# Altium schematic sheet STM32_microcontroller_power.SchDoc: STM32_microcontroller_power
size A3; DocumentNumber: MB1312; Revision: A-03; SheetNumber: 4; SheetTotal: 9; Project: NUCLEO-L4P5ZG
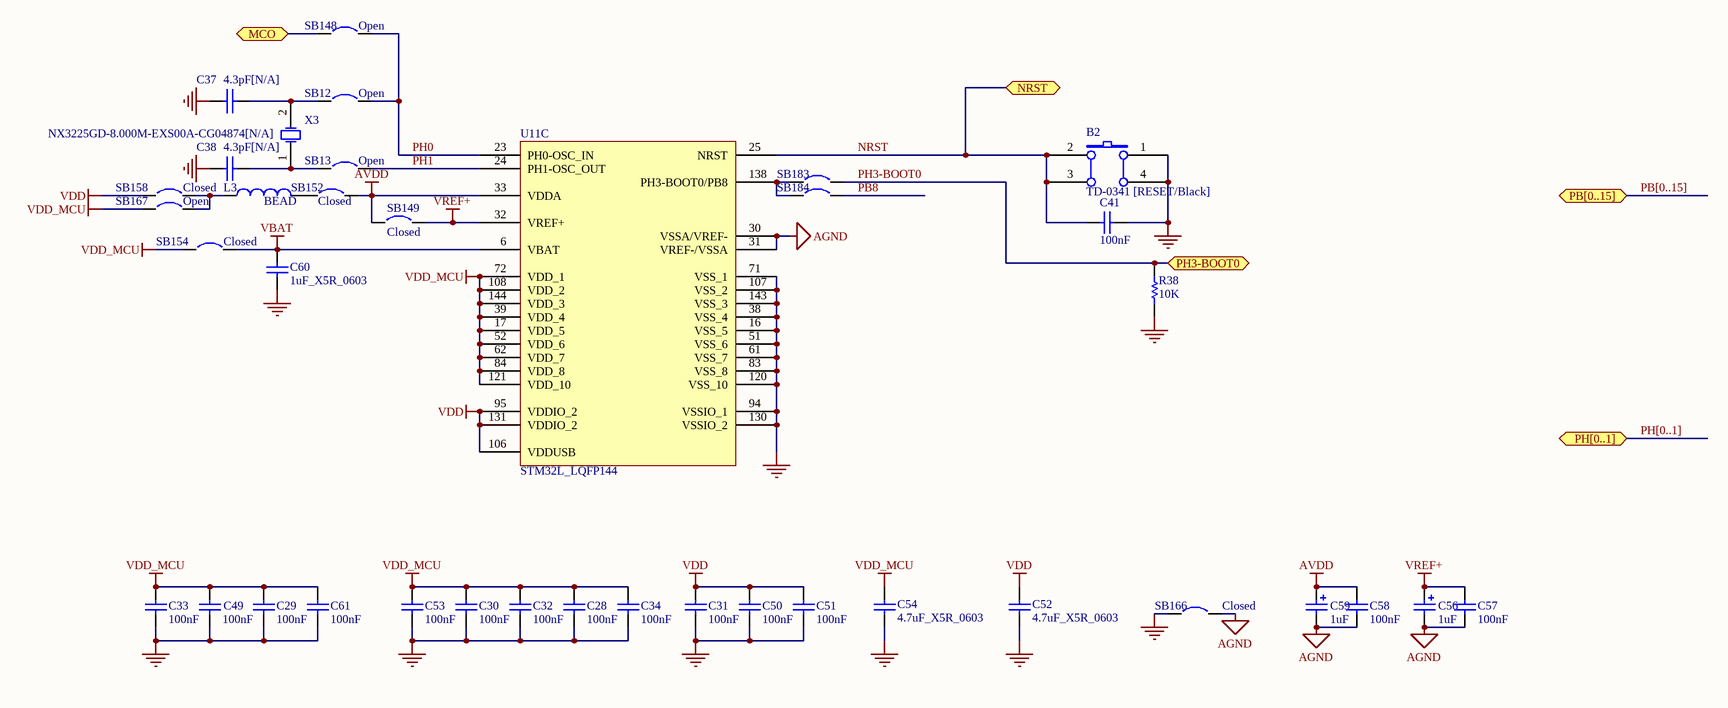
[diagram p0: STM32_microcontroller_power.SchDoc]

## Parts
B2  TD-0341 [RESET/Black]  [PB-6X6mm-Black]
C28  100nF  [0603C]
C29  100nF  [0603C]
C30  100nF  [0603C]
C31  100nF  [0603C]
C32  100nF  [0603C]
C33  100nF  [0603C]
C34  100nF  [0603C]
C37  4.3pF[N/A]  [0603C]
C38  4.3pF[N/A]  [0603C]
C41  100nF  [0603C]
C49  100nF  [0603C]
C50  100nF  [0603C]
C51  100nF  [0603C]
C52  4.7uF_X5R_0603  [0603C]
C53  100nF  [0603C]
C54  4.7uF_X5R_0603  [0603C]
C56  value 1uF  [TAN-A]  (hidden comment: TAJA105K016R)
C57  100nF  [0603C]
C58  100nF  [0603C]
C59  value 1uF  [TAN-A]  (hidden comment: TAJA105K016R)
C60  1uF_X5R_0603  [0603C]
C61  100nF  [0603C]
L3  BEAD  [0603L]
R38  10K  [0603R]
SB12  Open  [SB_0603]
SB13  Open  [SB_0603]
SB148  Open  [SB_0603]
SB149  Closed  [SB_0603]
SB152  Closed  [SB_0603]
SB154  Closed  [SB_0603]
SB158  Closed  [SB_0603]
SB166  Closed  [SB_0603]
SB167  Open  [SB_0603]
SB183  Circuit Breaker  [SB_0603]  (value not drawn)
SB184  Circuit Breaker  [SB_0603]  (value not drawn)
U11  STM32L_LQFP144  [LQFP144_0R5_SKT]  (part C of 3)
X3  NX3225GD-8.000M-EXS00A-CG04874[N/A]  [OSC_2SM_3R2x2R5]

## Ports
MCO, NRST, PB[0..15] (bidir), PH3-BOOT0, PH[0..1] (bidir)

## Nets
AGND: C56.2 C57.2 C58.2 C59.2 SB166.2 U11.30(VSSA/VREF-) U11.31(VREF-/VSSA)
AVDD: C58.1 C59.1 SB149.1 SB152.2 U11.33(VDDA)
GND: B2.1(A0) B2.4(A1) C28.2 C29.2 C30.2 C31.2 C32.2 C33.2 C34.2 C37.2 C38.2 C41.1 C49.2 C50.2 C51.2 C52.2 C53.2 C54.2 C60.2 C61.2 R38.2 SB166.1 U11.16(VSS_5) U11.38(VSS_4) U11.51(VSS_6) U11.61(VSS_7) U11.71(VSS_1) U11.83(VSS_8) U11.94(VSSIO_1) U11.107(VSS_2) U11.120(VSS_10) U11.130(VSSIO_2) U11.143(VSS_3)
VBAT: C60.1 SB154.2 U11.6(VBAT)
VDD: C31.1 C50.1 C51.1 C52.1 SB158.1 U11.95(VDDIO_2) U11.106(VDDUSB) U11.131(VDDIO_2)
VDD_MCU: C28.1 C29.1 C30.1 C32.1 C33.1 C34.1 C49.1 C53.1 C54.1 C61.1 SB154.1 SB167.1 U11.17(VDD_5) U11.39(VDD_4) U11.52(VDD_6) U11.62(VDD_7) U11.72(VDD_1) U11.84(VDD_8) U11.108(VDD_2) U11.121(VDD_10) U11.144(VDD_3)
VREF+: C56.1 C57.1 SB149.2 U11.32(VREF+)
MCO: SB148.2 ; port MCO
NRST: B2.2(B0) B2.3(B1) C41.2 U11.25(NRST) ; port NRST
PB8: SB184.2
PH0: SB12.2 SB148.1 U11.23(PH0-OSC_IN)
PH1: SB13.2 U11.24(PH1-OSC_OUT)
PH3-BOOT0: R38.1 SB183.2 ; port PH3-BOOT0
NetC37_1: C37.1 SB12.1 X3.2(OSC2)
NetC38_1: C38.1 SB13.1 X3.1(OSC1)
NetL3_1: L3.1 SB158.2 SB167.2
NetL3_2: L3.2 SB152.1
NetSB183_1: SB183.1 SB184.1 U11.138(PH3-BOOT0/PB8)

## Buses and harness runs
bus PB[0..15] = port PB[0..15]
bus PH[0..1] = port PH[0..1]

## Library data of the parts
B2 = SW PUSHBUTTON: SE PUSHBUTTON
C28-C34 C49-C51 C53 C57 C58 C61 = Cap: Capacitor; Value: 10nF
C37 C38 = CAP: Capacitor
C41 = CAP: Capacitor; Value: 100pF
C52 C54 = CAP SMD 0603  X5R 1µF 25V 10%: 0603  X5R 4.7uF; Value: 1µF; Rated voltage: 25V; Tolerance: 10%
C56 C59 = Cap Pol1: Tan Capacitor,1uF,10%,16V,Tan-A,TAJA105K016R; Manuf_1: AVX; Ordered by: Subcon; ECCN_US/EU: NA
C60 = CAP SMD 0603  X5R 1µF 25V 10%: 0603  X5R 1µF; Rated voltage: 25V; Tolerance: 10%
L3 = Inductor: Value: 100uH
R38 = res1: Resistor; Value: 1K
SB12 SB13 SB148 SB167 = Circuit Breaker
SB149 SB152 SB154 SB158 SB166 = Circuit Breaker_close: Circuit Breaker
SB183 SB184 = Circuit Breaker: Solder: NO
X3 = XTAL: Crystal Oscillator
